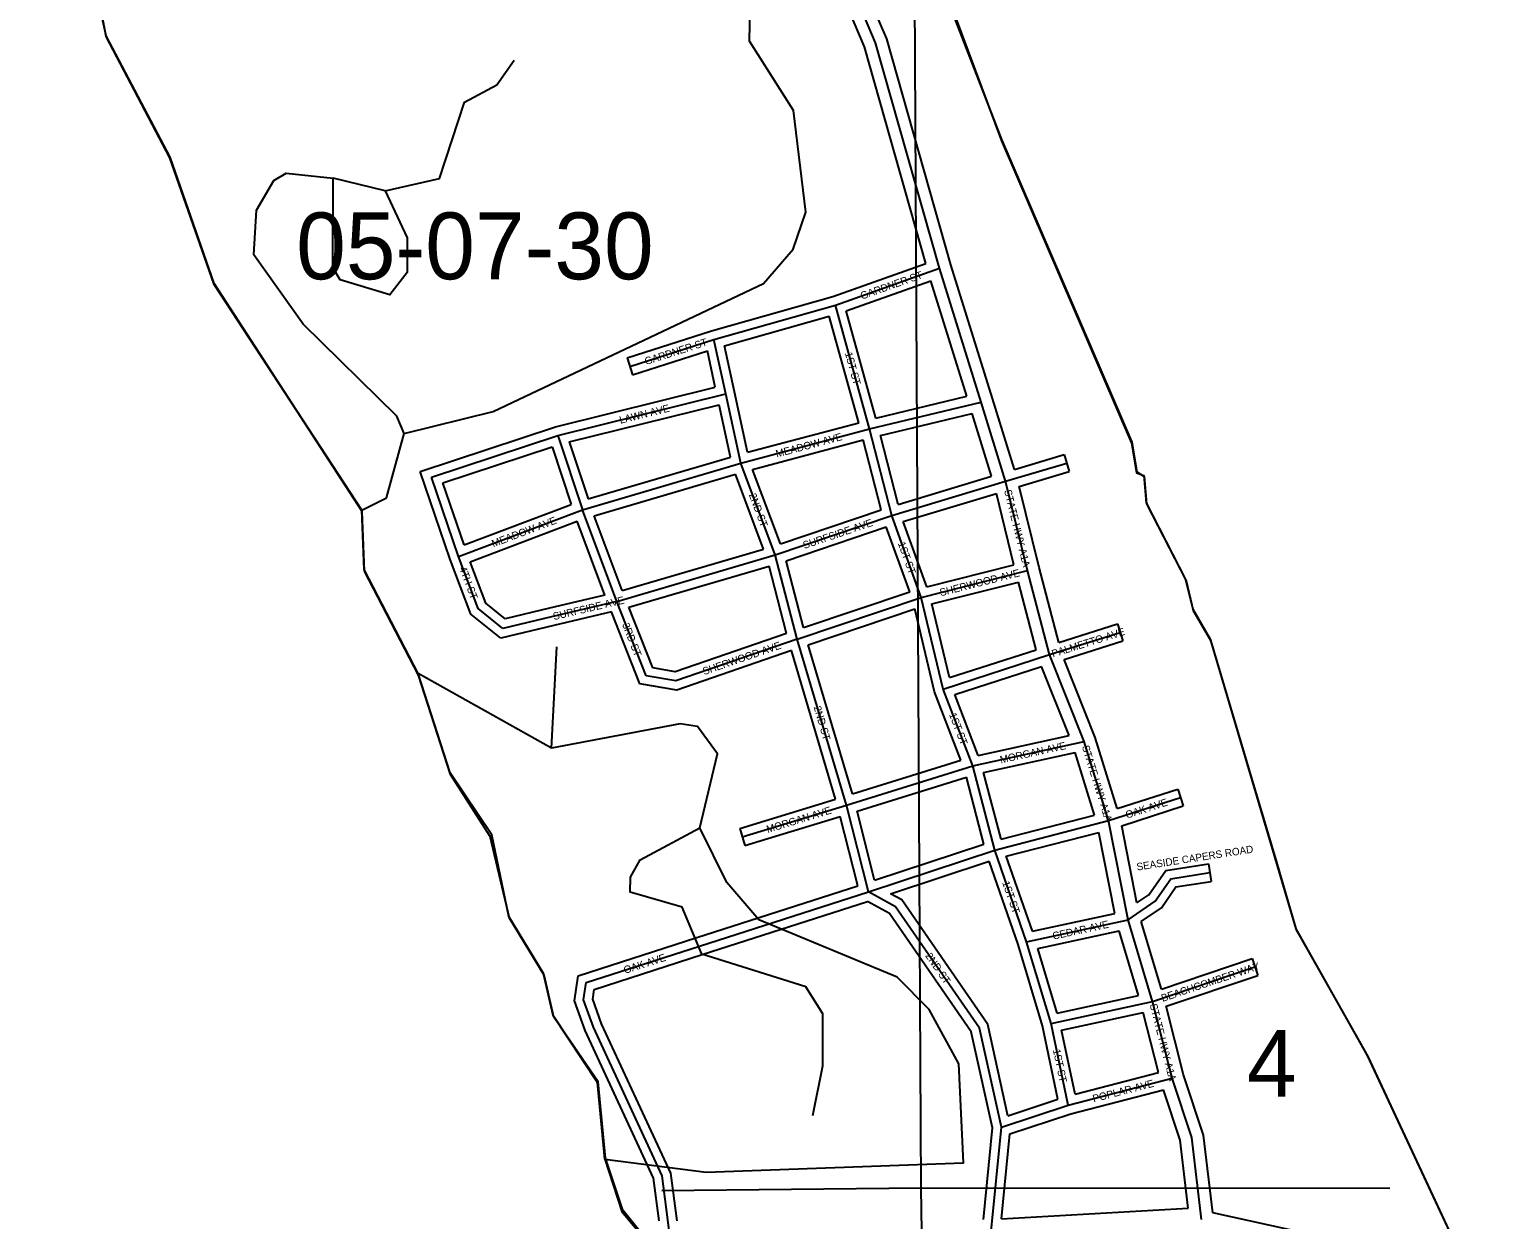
# Model space of a CAD drawing. Extents: x 418523 to 616617, y 1878279 to 2196743.
# Drawn here: x 559594 to 564582, y 2029851 to 2033859 of the extents above; entities that cross this region are included whole.
import ezdxf

# ---------------------------------------------------------------- set-up
doc = ezdxf.new("R2010")
doc.units = 0
for name, color, linetype in [('Level 1', 7, 'Continuous'), ('Level 2', 7, 'Continuous'), ('Level 22', 7, 'Continuous'), ('Level 23', 7, 'Continuous'), ('Level 31', 7, 'Continuous'), ('Level 32', 7, 'Continuous'), ('Level 34', 7, 'Continuous'), ('Level 5', 7, 'Continuous'), ('Level 7', 7, 'Continuous'), ('Level 8', 7, 'Continuous')]:
    doc.layers.add(name, color=color, linetype=linetype)

msp = doc.modelspace()

# ---------------------------------------------------------------- linework, layer by layer
at = {"layer": 'Level 1'}
for p, q in [((562597.423, 2029956.365), (562574.997, 2034070.471)), ((562597.423, 2029956.365), (561724.05, 2029947.847)), ((562655.833, 2025828.258), (562597.423, 2029956.365)), ((564176.3, 2029955.274), (562597.423, 2029956.365))]:
    msp.add_line(p, q, dxfattribs=at)
at = {"layer": 'Level 22'}
for p, q in [((562799.119, 2032604.201), (562658.663, 2033054.775)), ((562881.756, 2032337.426), (562799.119, 2032604.201)), ((562956.073, 2032036.851), (562881.756, 2032337.426)), ((563030.116, 2031753.368), (562956.073, 2032036.851)), ((563146.274, 2031461.414), (563030.116, 2031753.368)), ((563228.915, 2031194.276), (563146.274, 2031461.414)), ((563294.599, 2030860.631), (563228.915, 2031194.276)), ((563377.223, 2030585.491), (563294.599, 2030860.631)), ((563443.099, 2030326.761), (563377.223, 2030585.491))]:
    msp.add_line(p, q, dxfattribs=at)
for points in [[(562658.663, 2033054.775), (562443.921, 2033813.926), (562394.17, 2033930.791), (562361.356, 2034106.16), (562261.895, 2034356.251), (562146.35, 2034756.943)], [(563542.01, 2029851.203), (563509.44, 2030126.578), (563443.099, 2030326.761)]]:
    msp.add_lwpolyline(points, dxfattribs=at)
at = {"layer": 'Level 23'}
for p, q in [((562837.308, 2032616.106), (562697.01, 2033066.172)), ((562751.207, 2032623.488), (562629.869, 2033012.736)), ((562911.222, 2032377.489), (562837.329, 2032616.037)), ((562834.585, 2032354.527), (562769.055, 2032566.071)), ((562994.776, 2032046.958), (562927.349, 2032319.686)), ((562910.091, 2032056.168), (562850.622, 2032296.692)), ((563060.735, 2031794.427), (562994.776, 2032046.958)), ((562984.396, 2031770.127), (562924.874, 2031998.016)), ((563095.456, 2031480.938), (563003.084, 2031713.109)), ((563184.024, 2031474.738), (563079.508, 2031737.431)), ((563258.13, 2031235.19), (563184.024, 2031474.739)), ((563181.263, 2031212.965), (563115.972, 2031424.017)), ((563249.702, 2030881.606), (563195.923, 2031154.781)), ((563324.235, 2030917.182), (563273.092, 2031176.971)), ((563406.524, 2030627.002), (563338.314, 2030854.145)), ((563329.365, 2030605.781), (563264.039, 2030823.318)), ((563481.515, 2030338), (563422.668, 2030569.127)), ((563396.974, 2030345.801), (563345.52, 2030547.891)), ((562867.465, 2029853.53), (563497.288, 2029888.764))]:
    msp.add_line(p, q, dxfattribs=at)
for points in [[(562697.01, 2033066.172), (562481.72, 2033827.258), (562432.685, 2033942.44), (562399.96, 2034117.334), (562299.787, 2034369.215), (562184.951, 2034767.45)], [(562612.699, 2033070.31), (562406.123, 2033800.595), (562355.654, 2033919.141), (562322.752, 2034094.986), (562224.002, 2034343.288), (562116.808, 2034715.022)], [(563579.638, 2029873.617), (563548.687, 2030135.308), (563481.515, 2030337.999)], [(563497.289, 2029888.763), (563470.192, 2030117.848), (563413.75, 2030288.165)]]:
    msp.add_lwpolyline(points, dxfattribs=at)
at = {"layer": 'Level 31'}
for p, q in [((562308.29, 2032930.574), (562658.663, 2033054.775)), ((561899.331, 2032815.255), (562308.29, 2032930.574)), ((562423.802, 2032513.519), (562308.29, 2032930.574)), ((561615.567, 2032724.346), (561899.331, 2032815.255)), ((561939.093, 2032631.866), (561899.331, 2032815.255)), ((561373.251, 2032491.502), (561939.093, 2032631.866)), ((561989.811, 2032397.901), (561939.093, 2032631.866)), ((562423.802, 2032513.519), (562799.119, 2032604.201)), ((561989.811, 2032397.901), (562423.802, 2032513.519)), ((562498.136, 2032221.671), (562423.802, 2032513.519)), ((560947.745, 2032350.781), (561373.251, 2032491.502)), ((561373.251, 2032491.502), (561455.92, 2032241.087)), ((562881.756, 2032337.426), (563087.83, 2032398.721)), ((561038.922, 2032083.978), (560947.745, 2032350.781)), ((561455.92, 2032241.087), (561989.811, 2032397.901)), ((562105.916, 2032089.215), (561989.811, 2032397.901)), ((562498.136, 2032221.671), (562881.756, 2032337.426)), ((561038.922, 2032083.978), (561455.92, 2032241.087)), ((561572.021, 2031932.401), (561455.92, 2032241.087)), ((562105.916, 2032089.215), (562498.136, 2032221.671)), ((562597.224, 2031946.125), (562498.136, 2032221.671)), ((561572.021, 2031932.401), (562105.916, 2032089.215)), ((562179.953, 2031805.731), (562105.916, 2032089.215)), ((562597.224, 2031946.125), (562956.073, 2032036.851)), ((561572.021, 2031932.401), (561352.344, 2031880.603)), ((561671.166, 2031681.944), (561572.021, 2031932.401)), ((562179.953, 2031805.731), (562597.224, 2031946.125)), ((562671.517, 2031637.549), (562597.224, 2031946.125)), ((561352.344, 2031880.603), (561188.14, 2031841.754)), ((562345.475, 2031246.719), (562179.953, 2031805.731)), ((563030.116, 2031753.368), (563267.907, 2031828.041)), ((562671.517, 2031637.549), (563030.116, 2031753.368)), ((562770.967, 2031378.73), (562671.517, 2031637.549)), ((562770.967, 2031378.73), (563146.274, 2031461.414)), ((562345.475, 2031246.719), (562770.967, 2031378.73)), ((562845.01, 2031095.247), (562770.967, 2031378.73)), ((563228.915, 2031194.276), (563471.153, 2031272.211)), ((561994.811, 2031139.251), (562345.475, 2031246.719)), ((562419.495, 2030954.872), (562345.475, 2031246.719)), ((562845.01, 2031095.247), (563228.915, 2031194.276)), ((562419.495, 2030954.872), (562845.01, 2031095.247)), ((562952.572, 2030786.586), (562845.01, 2031095.247)), ((561850.351, 2030771.961), (562419.495, 2030954.872)), ((562952.572, 2030786.586), (563294.599, 2030860.631)), ((561468.276, 2030648.94), (561850.351, 2030771.961)), ((563035.193, 2030511.084), (562952.572, 2030786.586)), ((563377.223, 2030585.491), (563721.574, 2030701.355)), ((563035.193, 2030511.084), (563377.223, 2030585.491)), ((563092.788, 2030236.008), (563035.193, 2030511.084)), ((563092.788, 2030236.008), (563443.099, 2030326.761)), ((562867.66, 2030161.668), (563092.788, 2030236.008)), ((562833.185, 2029811.549), (562867.66, 2030161.668))]:
    msp.add_line(p, q, dxfattribs=at)
for points in [[(561188.14, 2031841.754), (561104.995, 2031908.52), (561038.922, 2032083.978)], [(562179.953, 2031805.731), (561771.232, 2031664.956), (561671.166, 2031681.944)], [(563294.599, 2030860.631), (563385.364, 2030922.586), (563438.464, 2030998.821), (563569.991, 2031019.215)], [(562867.66, 2030161.668), (562793.425, 2030495.336), (562511.24, 2030904.451), (562419.495, 2030954.872)], [(561749.649, 2029805.97), (561725.115, 2029998.046), (561492.915, 2030498.683), (561459.887, 2030590.412), (561468.276, 2030648.94)]]:
    msp.add_lwpolyline(points, dxfattribs=at)
at = {"layer": 'Level 32'}
for p, q in [((562299.2, 2032959.18), (562612.699, 2033070.311)), ((562344.666, 2032911.637), (562629.869, 2033012.737)), ((561890.683, 2032843.986), (562299.2, 2032959.18)), ((562444.968, 2032549.496), (562344.667, 2032911.637)), ((561934.63, 2032794.037), (562287.425, 2032893.519)), ((562386.803, 2032534.708), (562287.425, 2032893.519)), ((561606.415, 2032752.915), (561890.682, 2032843.986)), ((561606.415, 2032752.915), (561624.721, 2032695.775)), ((561624.721, 2032695.775), (561877.015, 2032776.602)), ((561903.603, 2032653.971), (561877.015, 2032776.601)), ((561968.412, 2032638.222), (561934.63, 2032794.036)), ((561364.918, 2032520.345), (561903.602, 2032653.972)), ((562012.47, 2032434.983), (561968.412, 2032638.221)), ((562444.968, 2032549.496), (562751.207, 2032623.489)), ((561411.885, 2032470.175), (561916.321, 2032595.306)), ((561954.58, 2032418.819), (561916.322, 2032595.306)), ((562460.372, 2032491.49), (562769.055, 2032566.071)), ((560909.558, 2032369.75), (561364.918, 2032520.345)), ((562012.47, 2032434.983), (562386.803, 2032534.708)), ((560985.932, 2032331.81), (561354.174, 2032453.593)), ((561354.174, 2032453.593), (561418.41, 2032259.013)), ((561411.885, 2032470.175), (561475.311, 2032278.05)), ((562029.56, 2032377.442), (562402.217, 2032476.721)), ((562462.205, 2032241.201), (562402.216, 2032476.721)), ((562519.474, 2032259.446), (562460.372, 2032491.49)), ((561475.311, 2032278.051), (561954.58, 2032418.82)), ((562911.223, 2032377.489), (563079.277, 2032427.477)), ((563079.277, 2032427.477), (563096.385, 2032369.966)), ((561010.684, 2032073.838), (560909.559, 2032369.749)), ((561495.375, 2032221.406), (561971.539, 2032361.265)), ((562066.462, 2032108.893), (561971.539, 2032361.265)), ((562123.789, 2032126.916), (562029.559, 2032377.442)), ((562519.474, 2032259.446), (562834.584, 2032354.527)), ((562927.349, 2032319.686), (563096.385, 2032369.966)), ((561057.305, 2032122.963), (560985.931, 2032331.811)), ((561057.305, 2032122.963), (561418.41, 2032259.013)), ((562537.064, 2032202.079), (562850.623, 2032296.693)), ((561077.57, 2032066.478), (561438.409, 2032202.429)), ((561531.933, 2031953.771), (561438.409, 2032202.429)), ((561590.295, 2031969.035), (561495.375, 2032221.406)), ((562123.79, 2032126.916), (562462.205, 2032241.2)), ((562616.248, 2031981.878), (562537.063, 2032202.079)), ((562142.01, 2032069.738), (562479.861, 2032183.833)), ((562558.63, 2031964.791), (562479.861, 2032183.833)), ((561590.296, 2031969.036), (562066.462, 2032108.894)), ((561612.015, 2031912.878), (562084.703, 2032051.715)), ((562143.903, 2031825.043), (562084.704, 2032051.716)), ((562200.857, 2031844.417), (562142.01, 2032069.738)), ((562616.248, 2031981.878), (562910.091, 2032056.168)), ((561531.932, 2031953.771), (561345.459, 2031909.803)), ((562200.857, 2031844.416), (562558.63, 2031964.791)), ((562633.335, 2031924.309), (562924.874, 2031998.017)), ((561345.436, 2031909.797), (561195.496, 2031874.322)), ((561692.843, 2031708.693), (561612.015, 2031912.878)), ((562216.93, 2031786.518), (562575.729, 2031907.239)), ((562642.81, 2031628.618), (562575.728, 2031907.238)), ((562693.107, 2031676.047), (562633.335, 2031924.309)), ((561359.252, 2031851.408), (561180.785, 2031809.184)), ((561553.67, 2031897.249), (561359.23, 2031851.402)), ((561649.491, 2031655.193), (561553.671, 2031897.249)), ((563060.735, 2031794.427), (563258.919, 2031856.663)), ((563258.919, 2031856.663), (563276.896, 2031799.418)), ((563079.508, 2031737.431), (563276.896, 2031799.418)), ((562308.273, 2031266.695), (562160.087, 2031767.156)), ((562365.613, 2031284.378), (562216.93, 2031786.518)), ((562693.107, 2031676.047), (562984.397, 2031770.127)), ((562710.885, 2031618.736), (563003.083, 2031713.109)), ((562731.468, 2031397.886), (562642.81, 2031628.619)), ((562789.715, 2031413.579), (562710.885, 2031618.736)), ((562789.715, 2031413.579), (563095.455, 2031480.937)), ((562807.875, 2031356.141), (563115.973, 2031424.018)), ((562365.613, 2031284.378), (562731.467, 2031397.886)), ((562866.479, 2031131.768), (562807.875, 2031356.141)), ((562381.555, 2031226.5), (562749.875, 2031340.773)), ((562808.867, 2031114.913), (562749.875, 2031340.773)), ((563258.13, 2031235.19), (563461.965, 2031300.771)), ((563461.965, 2031300.771), (563480.342, 2031243.651)), ((561986.02, 2031167.933), (562308.273, 2031266.695)), ((562003.603, 2031110.566), (562324.142, 2031208.802)), ((562383.487, 2030974.811), (562324.142, 2031208.802)), ((562440.662, 2030993.445), (562381.555, 2031226.5)), ((562866.479, 2031131.768), (563181.263, 2031212.965)), ((563273.092, 2031176.971), (563480.342, 2031243.651)), ((561986.02, 2031167.933), (562003.603, 2031110.566)), ((562884.067, 2031074.338), (563195.923, 2031154.781)), ((562440.662, 2030993.445), (562808.867, 2031114.913)), ((562494.34, 2030947.971), (562826.39, 2031057.513)), ((562924.026, 2030777.337), (562826.39, 2031057.513)), ((562972.168, 2030821.524), (562884.067, 2031074.338)), ((563565.394, 2031048.861), (563574.588, 2030989.569)), ((561841.172, 2030800.521), (562383.487, 2030974.811)), ((561859.531, 2030743.398), (562416.371, 2030922.356)), ((562972.168, 2030821.524), (563249.702, 2030881.606)), ((562990.629, 2030764.128), (563264.039, 2030823.318)), ((561441.239, 2030671.751), (561841.156, 2030800.516)), ((563006.092, 2030503.686), (562924.027, 2030777.336)), ((563055.952, 2030546.301), (562990.628, 2030764.128)), ((561495.315, 2030626.127), (561859.547, 2030743.403)), ((563406.523, 2030627.002), (563712.006, 2030729.788)), ((563712.006, 2030729.788), (563731.142, 2030672.92)), ((563422.668, 2030569.127), (563731.142, 2030672.92)), ((563055.953, 2030546.301), (563329.365, 2030605.781)), ((563057.932, 2030256.091), (563006.091, 2030503.687)), ((563070.659, 2030488.096), (563345.52, 2030547.891)), ((563115.708, 2030272.936), (563070.659, 2030488.096)), ((563115.708, 2030272.936), (563396.975, 2030345.801)), ((562889.744, 2030200.553), (563057.933, 2030256.091)), ((563101.263, 2030207.212), (563413.75, 2030288.165)), ((562895.604, 2030139.301), (563101.263, 2030207.212)), ((562806.955, 2029851.309), (562837.334, 2030159.835)), ((562867.465, 2029853.53), (562895.604, 2030139.301))]:
    msp.add_line(p, q, dxfattribs=at)
for points in [[(561180.785, 2031809.184), (561079.811, 2031890.267), (561010.684, 2032073.838)], [(561195.496, 2031874.322), (561130.179, 2031926.773), (561077.57, 2032066.479)], [(562143.902, 2031825.043), (561768.704, 2031695.816), (561692.844, 2031708.693)], [(562160.087, 2031767.157), (561773.761, 2031634.097), (561649.49, 2031655.193)], [(563324.235, 2030917.182), (563363.896, 2030944.256), (563421.183, 2031026.5), (563565.394, 2031048.861)], [(563338.313, 2030854.145), (563406.83, 2030900.916), (563455.745, 2030971.141), (563574.588, 2030989.569)], [(562837.335, 2030159.835), (562765.409, 2030483.114), (562490.572, 2030881.577), (562416.371, 2030922.356)], [(562889.743, 2030200.553), (562821.44, 2030507.557), (562531.907, 2030927.326), (562494.34, 2030947.971)], [(561714.302, 2029845.926), (561695.945, 2029989.637), (561465.14, 2030487.267), (561429.13, 2030587.276), (561441.239, 2030671.751)], [(561774.793, 2029845.905), (561754.285, 2030006.455), (561520.69, 2030510.099), (561490.643, 2030593.549), (561495.315, 2030626.127)], [(564090.635, 2029719.367), (564013.045, 2029777.922), (563579.639, 2029873.617)]]:
    msp.add_lwpolyline(points, dxfattribs=at)
at = {"layer": 'Level 5'}
for p, q in [((560791.35, 2033315.534), (560616.415, 2033357.802)), ((561352.156, 2031438.017), (561369.931, 2031779.776)), ((561352.156, 2031438.017), (560902.802, 2031689.588))]:
    msp.add_line(p, q, dxfattribs=at)
for points in [[(560712.827, 2032240.408), (560215.102, 2033000.61), (560066.451, 2033426.258), (559851.009, 2033835.425), (559801.843, 2034094.02), (559670.024, 2034290.608), (559586.431, 2034511.557), (559354.12, 2034862.432), (559296.255, 2035012.686)], [(562644.5, 2034084.822), (562867.655, 2033483.891), (563306.184, 2032465.413), (563322.536, 2032365.351), (563347.507, 2032356.911), (563355.559, 2032265.179), (563488.116, 2032006.325), (563512.799, 2031906.223), (563570.832, 2031805.991), (563859.436, 2030829.692), (564099.82, 2030403.756), (564497.224, 2029552.171), (564538.348, 2029376.977), (564621.123, 2029193.284)], [(560791.35, 2033315.534), (560974.884, 2033356.626), (561059.061, 2033614.793), (561167.633, 2033672.786), (561226.243, 2033755.949)], [(560855.396, 2032498.376), (560830.585, 2032556.796), (560514.782, 2032866.28), (560348.804, 2033100.224), (560357.631, 2033250.247), (560416.31, 2033350.09), (560458.091, 2033374.961), (560616.415, 2033357.802)], [(560791.35, 2033315.534), (560865.855, 2033156.911), (560865.467, 2033040.198), (560806.877, 2032965.376), (560640.322, 2033015.915), (560615.44, 2033057.696), (560616.415, 2033357.802)], [(560712.827, 2032240.408), (560796.329, 2032281.82), (560855.396, 2032498.376)], [(560902.802, 2031689.588), (560720.551, 2032040.294), (560712.827, 2032240.408)], [(561531.075, 2030053.598), (561506.92, 2030312.123), (561357.583, 2030537.696), (561324.7, 2030679.51), (561208.604, 2030871.602), (561151.137, 2031146.898), (561010.1, 2031355.771), (560902.802, 2031689.588)], [(561851.483, 2031169.657), (561910.62, 2031419.553), (561844.227, 2031511.475), (561785.905, 2031519.974), (561352.156, 2031438.017)], [(562231.82, 2030201.399), (562265.687, 2030368.023), (562266.284, 2030543.087), (562208.221, 2030634.989), (561858.45, 2030744.467), (561792.246, 2030903.09), (561617.351, 2030953.659), (561617.51, 2031003.681), (561651.05, 2031061.932), (561851.483, 2031169.657)], [(561531.075, 2030053.598), (561588.88, 2029878.374), (561671.914, 2029778.043), (561671.426, 2029627.99), (561579.336, 2029511.576), (561585.975, 2028986.384), (561635.54, 2028844.501), (561651.723, 2028686.048), (561725.929, 2028435.723), (561833.615, 2028226.96), (562057.626, 2027892.785), (562265.285, 2027658.681)]]:
    msp.add_lwpolyline(points, dxfattribs=at)
at = {"layer": 'Level 7'}
for points in [[(560855.396, 2032498.376), (561155.732, 2032572.421), (562065.805, 2033002.961), (562166.225, 2033119.345), (562208.305, 2033244.258), (562167.728, 2033586.186), (562018.43, 2033820.089), (562028.232, 2034278.56)], [(561531.075, 2030053.598), (561872.745, 2030010.841), (562739.824, 2030041.371), (562724.228, 2030374.859), (562624.772, 2030558.582), (562516.758, 2030667.313), (562050.543, 2030860.552), (561942.569, 2030985.964), (561851.483, 2031169.657)]]:
    msp.add_lwpolyline(points, dxfattribs=at)
at = {"layer": 'Level 8'}
for points in [[(561653.913, 2029805.983), (561591.91, 2029881.985), (561533.905, 2030056.988), (561508.9, 2030314.993), (561359.893, 2030531.996), (561326.89, 2030674), (561210.884, 2030866.002), (561144.877, 2031141.008), (561011.87, 2031350.011), (560903.862, 2031684.017), (560721.851, 2032035.023), (560713.848, 2032235.028), (560215.822, 2033003.04), (560066.811, 2033429.048), (559851.799, 2033838.055), (559793.793, 2034096.06)], [(562635.86, 2034089.092), (562867.875, 2033488.081), (563306.904, 2032469.063), (563323.906, 2032369.061), (563348.907, 2032353.061), (563356.909, 2032261.059), (563489.916, 2032002.055), (563513.919, 2031902.053), (563571.922, 2031802.051), (563706.933, 2031348.042), (563793.94, 2031054.036), (563860.946, 2030826.032), (563897.948, 2030761.031), (564101.96, 2030400.026), (564499.984, 2029548.011), (564505.985, 2029523.011), (564540.988, 2029373.007), (564623.993, 2029198.004)]]:
    msp.add_lwpolyline(points, dxfattribs=at)

# ---------------------------------------------------------------- texts
at = {"layer": 'Level 2'}
for s, p in [('05-07-30', (560491.746, 2033017.679)), ('4', (563694.705, 2030264.318))]:
    msp.add_text(s, height=225, dxfattribs=at).set_placement(p)
at = {"layer": 'Level 34'}
for s, height, rotation, p in [('GARDNER ST', 24.9992, 19.517886, (562397.71, 2032949.011)), ('GARDNER ST', 25, 17.763181, (561670.38, 2032728.782)), ('1ST ST', 25, 285.480136, (562340.128, 2032768.794)), ('LAWN AVE', 25, 13.931042, (561583.979, 2032530.898)), ('MEADOW AVE', 25, 14.916983, (562110.96, 2032417.242)), ('STATE HWY A1A', 25, 283.886578, (562876.712, 2032305.751)), ('2ND ST', 25, 290.611656, (562016.371, 2032291.78)), ('MEADOW AVE', 25, 20.643886, (561155.891, 2032114.691)), ('SURFSIDE AVE', 25, 18.659617, (562203.97, 2032109.137)), ('1ST ST', 25, 289.777711, (562518.332, 2032128.572)), ('4TH ST', 25, 290.633953, (561040.281, 2032044.901)), ('SHERWOOD AVE', 25, 14.187717, (562663.371, 2031949.957)), ('SURFSIDE AVE', 25, 13.266803, (561360.21, 2031869.616)), ('3RD ST', 25, 291.595658, (561589.279, 2031854.846)), ('PALMETTO AVE', 25, 17.432964, (563041.423, 2031743.819)), ('SHERWOOD AVE', 25, 19.004408, (561866.203, 2031684.449)), ('2ND ST', 25, 286.492914, (562234.766, 2031576.585)), ('1ST ST', 25, 291.01802, (562690.933, 2031552.166)), ('MORGAN AVE', 25, 12.423783, (562865.804, 2031386.826)), ('STATE HWY A1A', 25, 287.1889, (563138.63, 2031443.831)), ('OAK AVE', 25, 17.833944, (563290.449, 2031200.944)), ('MORGAN AVE', 25, 17.038183, (562080.301, 2031152.38)), ('SEASIDE CAPERS ROAD', 25, 8.813644, (563324.905, 2031025.97)), ('1ST ST', 25, 289.211533, (562869.886, 2030985.879)), ('CEDAR AVE', 25, 12.214464, (563042.653, 2030793.301)), ('OAK AVE', 25, 17.846811, (561599.735, 2030678.136)), ('2ND ST', 25, 304.594789, (562610.123, 2030739.077)), ('BEACHCOMBER WAY', 25, 18.595697, (563410.99, 2030583.667)), ('STATE HWY A1A', 25, 284.28355, (563367.138, 2030574.446)), ('1ST ST', 25, 281.824572, (563041.106, 2030421.851)), ('POPLAR AVE', 25, 14.523172, (563178.693, 2030245.351))]:
    msp.add_text(s, height=height, rotation=rotation, dxfattribs=at).set_placement(p)

doc.saveas('drawing.dxf')
